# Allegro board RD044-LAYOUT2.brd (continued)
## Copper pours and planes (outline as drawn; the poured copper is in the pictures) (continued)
GND on TOP: 47.13,50.15 47.07,50.16 47.02,50.19 46.04,51.17 46.01,51.22 46,51.28 46,51.48 46.04,51.58 46.15,51.62 51.63,51.62 51.69,51.61 51.74,51.58 52,51.33 52.1,51.28 52.17,51.22 52.2,51.14 52.2,50.35 52.16,50.24 52.05,50.2 51.74,50.2 51.64,50.24 51.6,50.33 50.78,51.05 50,50.29 49.95,50.19 49.85,50.15
GND on BOTTOM: 31.09,61.22 31.06,61.27 31.05,61.33 31.05,65.42 31.06,65.48 31.09,65.53 33.67,68.11 33.72,68.14 33.78,68.16 35.91,68.16 35.98,68.14 36.03,68.09 36.09,68.01 36.24,67.83 36.43,67.68 36.48,67.63 36.5,67.55 36.5,67.13 36.49,67.07 36.46,67.02 34.53,65.09 34.48,65.06 34.43,65.05 33.93,64.82 33.7,64.32 33.69,64.27 33.66,64.22 32.59,63.16 32.47,62.97 32.42,62.75 32.42,60.25 32.33,60.11 32.17,60.14
GND on BOTTOM: 70.26,4.8 70.12,4.89 70.15,5.06 70.92,5.83 71.05,6.02 71.1,6.25 71.1,6.42 71.2,6.56 71.37,6.51 72.27,6.25 72.8,7.03 72.8,7.05 72.8,7.63 72.8,7.66 72.88,7.88 72.9,8.07 72.9,8.65 72.94,8.76 73.05,8.8 74.8,8.8 74.91,8.76 74.95,8.65 74.99,8.39 75.12,8.16 75.16,8.09 75.18,8.03 75.18,7.97 75.82,6.96 76.75,7.71 76.8,7.81 76.9,7.85 78.25,7.85 78.82,8.08 79.09,8.76 79.2,8.8 80.95,8.8 81.06,8.76 81.1,8.65 81.09,8.15 81.06,8.1 77.8,4.84 77.75,4.81 77.69,4.8
GND on BOTTOM: 37.27,4.54 37.24,4.59 37.23,4.65 37.23,6.75 37.32,6.89 37.48,6.86 37.54,6.81 37.6,6.76 37.66,6.71 37.67,6.64 37.67,4.5 37.58,4.36 37.42,4.39
GND on BOTTOM: 72.01,61.2 71.97,61.21 71.93,61.22 71.75,61.31 71.56,61.35 71.46,61.4 71.42,61.5 71.42,62.75 71.47,62.86 71.58,62.9 75.22,62.9 75.28,62.89 75.33,62.86 75.38,62.81 75.41,62.76 75.42,62.7 75.42,61.35 75.38,61.24 75.28,61.2
GND on BOTTOM: 75.12,57.15 75.08,57.04 74.97,57 74.76,57 73.95,56.2 74.76,55.4 74.97,55.4 75.08,55.36 75.12,55.25 75.12,54.83 75.08,54.72 74.97,54.67 72.45,54.67 72.39,54.69 72.34,54.72 71.47,55.59 71.44,55.64 71.42,55.7 71.42,59.25 71.47,59.36 71.58,59.4 74.97,59.4 75.08,59.36 75.12,59.25 ; 1 cut-out
GND on BOTTOM: 61.96,6.8 61.82,6.91 61.88,7.08 62.14,7.35 62.25,7.71 62.3,7.81 62.4,7.85 63.75,7.85 64.32,8.08 64.59,8.76 64.7,8.8 66.45,8.8 66.56,8.76 66.6,8.65 66.59,8.15 66.56,8.1 65.3,6.84 65.25,6.81 65.19,6.8
GND on BOTTOM: outline of 85 points within 33.58,52.66 46.5,67.9
GND on BOTTOM: 14,1.9 13.97,1.97 13.9,2 12.65,2 12.54,2.04 12.5,2.15 12.5,12.4 12.47,12.47 12.4,12.5 0.65,12.5 0.54,12.54 0.5,12.65 0.5,62.35 0.54,62.46 0.65,62.5 12.4,62.5 12.47,62.53 12.5,62.6 12.5,72.85 12.54,72.96 12.65,73 13.9,73 13.97,73.03 14,73.1 14,74.35 14.04,74.46 14.15,74.5 85.85,74.5 85.96,74.46 86,74.35 86,73.1 86.03,73.03 86.1,73 87.35,73 87.46,72.96 87.5,72.85 87.5,62.6 87.53,62.53 87.6,62.5 99.35,62.5 99.46,62.46 99.5,62.35 99.5,12.65 99.46,12.54 99.35,12.5 87.6,12.5 87.53,12.47 87.5,12.4 87.5,2.15 87.46,2.04 87.35,2 50.78,1.97 50.75,1.9 50.75,0.65 50.71,0.54 50.6,0.5 14.15,0.5 14.04,0.54 14,0.65 ; 31 cut-outs
GND on BOTTOM: 56.11,6.8 56.05,6.81 56,6.84 55.68,7.17 55.66,7.35 55.82,7.42 56.17,7.42 56.48,7.56 56.54,7.59 56.58,7.6 56.64,7.6 56.69,7.59 56.74,7.56 56.76,7.54 57.04,7.36 57.37,7.3 57.6,7.3 58.17,7.53 58.4,8.1 58.4,8.65 58.44,8.76 58.55,8.8 60.3,8.8 60.41,8.76 60.45,8.65 60.49,8.39 60.62,8.16 60.66,8.09 60.68,8.03 60.68,7.97 60.7,7.47 61.02,7.08 61.08,6.91 60.94,6.8
GND on BOTTOM: outline of 108 points within 40.45,45.67 66.7,53.5
GND on BOTTOM: 61.95,11.6 61.83,11.63 61.76,11.64 61.65,11.72 61.64,11.85 61.69,12 61.7,12.15 61.7,16.3 61.74,16.41 62.42,16.68 62.69,17.36 62.8,17.4 63.05,17.4 63.17,17.37 63.24,17.36 63.35,17.28 63.36,17.15 63.31,17 63.3,16.85 63.3,15.44 63.26,15.34 63.17,15.29 62.5,14.5 63.17,13.71 63.26,13.66 63.3,13.56 63.3,12.7 63.26,12.59 62.58,12.32 62.31,11.64 62.2,11.6
GND on BOTTOM: 82.39,10.64 82.1,10.7 81.35,10.7 81.24,10.74 81.2,10.85 81.2,12.8 81.24,12.9 81.34,12.95 81.88,13.2 82.1,13.75 82.1,15.25 81.88,15.8 81.34,16.05 81.24,16.1 81.2,16.2 81.2,16.65 81.24,16.76 81.35,16.8 82.05,16.79 82.1,16.76 82.86,16 82.89,15.95 82.9,15.89 82.9,10.59 82.81,10.46 82.65,10.48
GND on BOTTOM: 42.45,48.62 42.34,48.67 42.3,48.77 42.3,49.24 42.07,49.81 41.49,50.05 41.35,50.05 41.24,50.09 41.2,50.2 41.2,51.7 41.24,51.81 41.35,51.85 43.56,51.85 43.72,51.86 43.87,51.9 44.11,51.99 44.14,52 44.16,52 45.88,52 45.93,51.99 45.98,51.96 46.72,51.22 46.96,51.06 47.25,51 49.85,51 49.96,50.96 50,50.85 50,50.26 50.8,49.45 51.6,50.26 51.6,50.85 51.64,50.96 51.75,51 52.85,51 52.96,50.96 53,50.85 53,49.7 52.99,49.64 52.96,49.59 52.03,48.67 51.99,48.64 51.93,48.62
GND on BOTTOM: 71.1,15.89 71.11,15.95 71.14,16 71.9,16.76 71.95,16.79 72.65,16.8 72.76,16.76 72.8,16.65 72.8,16.2 72.76,16.1 72.66,16.05 72.12,15.8 71.9,15.25 71.9,13.75 72.12,13.2 72.66,12.95 72.76,12.9 72.8,12.8 72.8,10.85 72.76,10.74 72.65,10.7 71.9,10.7 71.61,10.64 71.35,10.48 71.19,10.46 71.1,10.59
GND on BOTTOM: 67.89,10.64 67.6,10.7 66.85,10.7 66.74,10.74 66.7,10.85 66.7,12.8 66.74,12.9 66.84,12.95 67.38,13.2 67.6,13.75 67.6,15.25 67.38,15.8 66.84,16.05 66.74,16.1 66.7,16.2 66.7,16.65 66.74,16.76 66.85,16.8 67.55,16.79 67.6,16.76 68.36,16 68.39,15.95 68.4,15.89 68.4,10.59 68.31,10.46 68.15,10.48
GND on BOTTOM: 52,10.84 51.97,11.01 52.11,11.1 54.7,11.1 54.93,11.15 55.12,11.28 56.67,12.83 56.8,13.02 56.85,13.25 56.85,16.14 56.86,16.2 56.89,16.25 57.4,16.76 57.45,16.79 58.15,16.8 58.26,16.76 58.3,16.65 58.3,16.2 58.26,16.1 57.62,15.8 57.4,15.25 57.4,13.75 57.62,13.2 58.16,12.95 58.26,12.9 58.3,12.8 58.3,10.85 58.26,10.74 58.15,10.7 57.4,10.7 56.83,10.47 56.6,9.9 56.6,9.15 56.56,9.04 56.45,9 56.01,9 55.38,8.7 55.22,8.02 55.15,7.86 54.97,7.88
GND on BOTTOM: 66.46,5.8 66.32,5.89 66.36,6.06 67.56,7.26 67.6,7.29 67.65,7.3 67.72,7.31 67.78,7.32 67.92,7.28 67.96,7.15 68.62,6.21 69.54,6.89 69.59,7.15 69.6,7.25 69.75,7.39 69.9,7.24 69.9,6.56 69.89,6.5 69.86,6.45 69.25,5.84 69.2,5.81 69.14,5.8
GND on BOTTOM: 76.45,11.6 76.33,11.63 76.26,11.64 76.15,11.72 76.14,11.85 76.19,12 76.2,12.15 76.2,16.3 76.24,16.41 76.92,16.68 77.19,17.36 77.3,17.4 77.55,17.4 77.67,17.37 77.74,17.36 77.85,17.28 77.86,17.15 77.81,17 77.8,16.85 77.8,15.44 77.76,15.34 77.67,15.29 77,14.5 77.67,13.71 77.76,13.66 77.8,13.56 77.8,12.7 77.76,12.59 77.08,12.32 76.81,11.64 76.7,11.6
GND on CONDUCTIVE2: 2,1 1.5,1.13 1.13,1.5 1,2 1,73 1.13,73.5 1.5,73.87 2,74 5.5,74 5.85,73.85 6,73.5 6,73.21 5.83,72.83 5.42,72.72 3.87,67.49 6.76,72.12 6.61,72.67 7.08,73 13.9,73 13.97,73.03 14,73.1 14,73.5 14.15,73.85 14.5,74 85.5,74 85.85,73.85 86,73.5 86,73.1 86.03,73.03 86.1,73 92.92,73 93.39,72.67 93.24,72.12 96.13,67.49 94.58,72.72 94.17,72.83 94,73.21 94,73.5 94.15,73.85 94.5,74 98,74 98.5,73.87 98.87,73.5 99,73 99,2.5 98.85,2.15 98.5,2 97.08,2 96.61,2.33 96.76,2.88 95,7.75 93.24,2.88 93.39,2.33 92.92,2 50.85,2 50.78,1.97 50.75,1.9 50.75,1.5 50.6,1.15 50.25,1 14.5,1 14.15,1.15 14,1.5 14,1.9 13.97,1.97 13.9,2 7.08,2 6.61,2.33 6.76,2.88 3.87,7.51 5.42,2.28 5.83,2.17 6,1.79 6,1.5 5.85,1.15 5.5,1
N16840741 on TOP: 12.42,39.5 8.65,39.5 8.54,39.54 8.5,39.65 8.5,42.42 8.51,42.47 8.56,42.56 8.94,42.94 8.98,42.97 9.08,43 12.85,43 12.96,42.96 13,42.85 13,40.08 12.99,40.03 12.94,39.94 12.56,39.56 12.52,39.53 ; 1 cut-out
N16841842 on TOP: 12.42,55.5 8.65,55.5 8.54,55.54 8.5,55.65 8.5,58.42 8.51,58.47 8.56,58.56 8.94,58.94 8.98,58.97 9.08,59 12.85,59 12.96,58.96 13,58.85 13,56.08 12.99,56.03 12.94,55.94 12.56,55.56 12.52,55.53 ; 1 cut-out

Small or netless copper shapes (teardrops, artwork), in the pictures only: 1076 on TOP, 603 on BOTTOM

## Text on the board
Ref Des/Silkscreen Top: GND | 1.2V | 3.3VA | 3.3V | 5V | RESET | 3V_REF
SYMBOL-1-TOP: R96 | R98 | R99 | R97 | R100 | R101 | R102 | R103 | R85 | R87 | D17 | 20 | 1 | D19 | D21 | D23 | D15 | D16 | D18 | D20 | D22 | D24 | PAD8 | PAD6 | PAD4 | PAD2 | R83 | R15 | R17 | R29 | R28 | R26 | PAD1 | PAD7 | PAD5 | PAD3 | C54 | C55 | C56 | R35 | R49 | R47 | R45 | R43 | D6 | C49 | C50 | R34 | R33 | R32 | R31 | R30 | R41 | R40 | R39 | R38 | R37 | R36 | 133 | 176 | 132 | C18 | C19 | C17 | R48 | R46 | R44 | R42 | C30 | R24 | R23 | R22 | C69 | D2 | D1 | C8 | C9 | D4 | D3 | 89 | 44 | D5 | 45 | 88 | C60 | PAD21 | C40 | R59 | C36 | C35 | C64 | C39 | C38 | C37 | PAD22 | C96 | C95 | LED1 | C85 | R81 | PAD18 | PAD19 | C83 | C90 | C84 | TP13 | R75 | R74 | R77 | R76 | C76 | R79 | R78 | R82 | R80 | PAD | 11 | 10 | 12 | 13 | 8 | 15 | 14 | 16 | 17 | C77 | C57 | R25 | C48 | C6 | R19 | R16 | R18 | R72 | C74 | R70 | C43 | C72 | C42 | C65 | R60 | C41 | C63 | R58 | C66 | C12 | R12 | R61 | C13 | R13 | C89 | C88 | C79 | C87 | C75 | C73 | C94 | PAD20 | C91 | C86 | R73 | R71 | C93 | C81 | C97 | C82 | C92 | CN6 | CN7 | TP25 | 4 | CN4 | FU2 | FU1 | IC11 | 3 | TP14 | TP12 | TP10 | TP6 | TP4 | TP8 | TP2 | CN2 | 2 | TP11 | TP5 | TP3 | TP9 | TP7 | TP1 | IC8 | CN3 | X1 | IC3 | CN1 | TP24 | PS2 | PS1 | IC15 | CN5 | 59 | 60 | IC12 | ON | PAD9 | SW2 | SW1 | IC5 | IC6 | IC7 | IC4 | IC10 | IC9 | L1 | HSP0179-B00-0002A
SYMBOL-1-BOTTOM: R68 | C70 | C67 | R64 | R57 | C62 | C59 | R53 | R86 | C78 | IC13 | IC14 | C80 | R88 | R90 | R92 | R94 | R89 | R91 | R93 | R95 | R84 | IC2 | R5 | C1 | C5 | R7 | C3 | C4 | R4 | R2 | 2 | 1 | C7 | C2 | R3 | R6 | R21 | R20 | R1 | C47 | R69 | C71 | C68 | R65 | C20 | C31 | D14 | D12 | C25 | C46 | C32 | C24 | D13 | D11 | C33 | R8 | R14 | C44 | C34 | C21 | R9 | R11 | D8 | C10 | D10 | C11 | R10 | D9 | D7 | R56 | C61 | C58 | R52 | 16 | 15 | 14 | 13 | IC1 | C28 | C51 | C52 | C53 | C26 | C29 | R67 | R63 | C27 | C45 | R62 | R66 | R55 | R51 | C16 | C23 | C22 | C15 | C14 | R54 | R50
